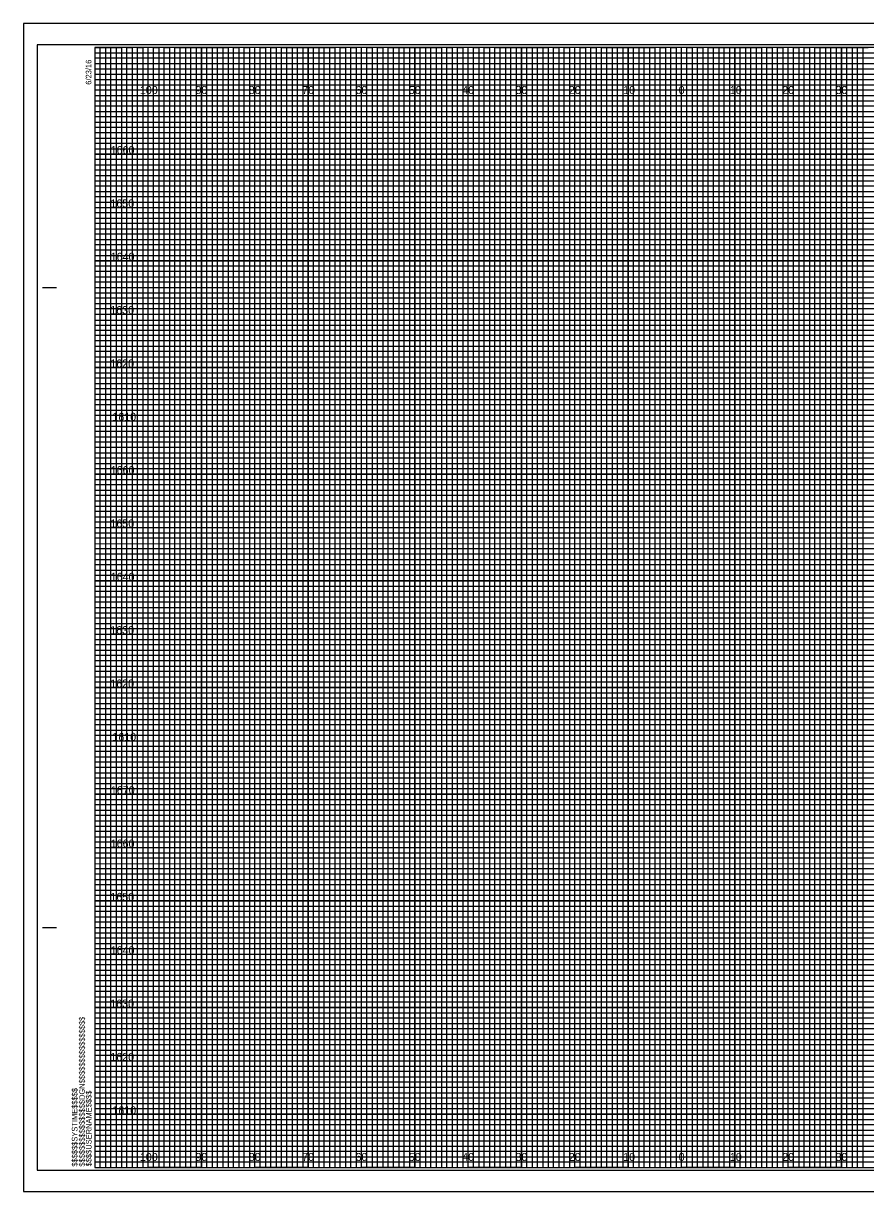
# Model space of a CAD drawing. Extents: x -13 to 323, y -5 to 6154.
# Drawn here: x -13.4 to 144.5, y 4175.5 to 4394.5 of the extents above; entities that cross this region are included whole.
import ezdxf

# ---------------------------------------------------------------- set-up
doc = ezdxf.new("R2010")
doc.units = 0
for name, color, linetype in [('Prop Retaining Wall', 7, 'Continuous'), ('Prop XS Alignment Label', 7, 'Continuous'), ('Prop XS DDE', 7, 'Continuous'), ('Prop XS DDE Elevations', 7, 'Continuous'), ('Prop XS DDE Slope Text', 7, 'Continuous'), ('Prop XS Earthwork Shape', 7, 'Continuous'), ('Prop XS Elevation Labels', 7, 'Continuous'), ('Prop XS Station Labels', 7, 'Continuous'), ('Raster_Level_0', 7, 'Continuous'), ('Scratch_Level_3', 7, 'Continuous'), ('Sheet Cutting Line CELL', 7, 'Continuous')]:
    doc.layers.add(name, color=color, linetype=linetype)

msp = doc.modelspace()

# ---------------------------------------------------------------- linework, layer by layer
at = {"layer": 'Prop Retaining Wall'}
for p, q in [((0, 4389), (260, 4389)), ((260, 4387.98), (0, 4387.98)), ((0, 4387.98), (0, 4387)), ((0, 4387), (260, 4387)), ((260, 4385.89), (0, 4385.89)), ((0, 4385.89), (0, 4384)), ((0, 4384), (320, 4384))]:
    msp.add_line(p, q, dxfattribs=at)
for points in [[(0, 4383), (270, 4383), (320, 4383), (320, 4382), (0, 4382)], [(0, 4381), (320, 4381), (320, 4379), (0, 4379)], [(0, 4378), (320, 4378), (320, 4377), (0, 4376.98)], [(0, 4376), (320, 4376), (320, 4374), (0, 4374)], [(0, 4373), (320, 4373), (320, 4372), (0, 4372)], [(0, 4371), (320, 4371), (320, 4369), (0, 4369)], [(0, 4368), (320, 4368), (320, 4367), (0, 4367)], [(0, 4366), (320, 4366), (320, 4364), (0, 4364)], [(0, 4363), (320, 4363), (320, 4362), (0, 4362)], [(0, 4361), (320, 4361), (320, 4359), (0, 4359)], [(0, 4358), (320, 4358), (320, 4357), (0, 4357)], [(0, 4356), (320, 4356), (320, 4353.95), (320, 4353), (320, 4352), (0, 4352)], [(0, 4354), (320, 4354), (320, 4353), (0, 4353)], [(0, 4351), (320, 4351), (320, 4349), (0, 4349.03)], [(0, 4349.03), (320, 4349), (320, 4348), (0, 4348)], [(0, 4347), (320, 4347), (320, 4346), (0, 4346)], [(0, 4344), (320, 4344), (320, 4343), (0, 4343)], [(0, 4342), (320, 4342), (320, 4341), (0, 4341)], [(-0.07, 4338.89), (320, 4338.89), (320, 4337.88), (-0.07, 4337.88)], [(0, 4337), (320, 4337), (320, 4336), (0, 4336)], [(0, 4334), (320, 4334), (320, 4333), (0, 4333)], [(0, 4332), (320, 4332), (320, 4331), (0, 4331)], [(0, 4329), (320, 4329), (320, 4328), (0, 4328)], [(0, 4327), (320, 4327), (320, 4326), (0, 4326)], [(0, 4324), (320, 4324), (320, 4323), (0, 4323)], [(0, 4322), (320, 4322), (320, 4321), (0, 4321)], [(0, 4319), (320, 4319), (319.99, 4317.98), (0, 4318)], [(0, 4317), (320, 4317), (320, 4316), (0, 4316)], [(0, 4314), (320, 4314), (320, 4313), (0, 4313)], [(0, 4312), (320, 4312), (320, 4311), (0, 4311)], [(0, 4309), (320, 4309), (320, 4308), (0, 4308)], [(0, 4307), (320, 4307), (320, 4306), (0, 4306)], [(0, 4304), (320, 4304), (320, 4303), (0, 4303)], [(0, 4302), (320, 4302), (320, 4301), (0, 4301)], [(0, 4299), (320, 4299), (320, 4298), (0, 4298)], [(0, 4296.99), (320.07, 4296.91), (320, 4296), (0, 4296)], [(0, 4294), (320, 4294), (320, 4293), (0, 4293)], [(0, 4292), (320, 4292), (320, 4291), (0, 4291)], [(0, 4289), (320, 4289), (320, 4288), (0, 4288)], [(0, 4287), (320, 4287), (320, 4286), (0, 4286)], [(0, 4284), (320, 4284), (320, 4283), (0, 4283)], [(0, 4282), (320, 4282), (320, 4281), (0, 4281)], [(0, 4279), (320, 4279), (320, 4278), (0, 4278)], [(0, 4277), (320, 4277), (320, 4276), (0, 4276)], [(0, 4274), (320, 4274), (320, 4273), (0, 4273)], [(0, 4272), (320, 4272), (320, 4271), (0, 4271)], [(0, 4269), (320, 4269), (320, 4268), (0, 4268)], [(0, 4267), (320, 4267), (320, 4266), (0, 4266)], [(0, 4264), (320, 4264), (320, 4263), (0, 4263)], [(0, 4262), (320, 4262), (320, 4261), (0, 4261)], [(0, 4259), (320, 4259), (319.99, 4257.98), (0, 4258)], [(0, 4257), (320, 4257), (320, 4256), (0, 4256)], [(0, 4254), (320, 4254), (320, 4253), (0, 4253)], [(0, 4252), (320, 4252), (320, 4251), (0, 4251)], [(0, 4249), (320, 4249), (320, 4248), (0, 4248)], [(0, 4247), (320, 4247), (320, 4246), (0, 4246)], [(0, 4244), (320, 4244), (320, 4243), (0, 4243)], [(0, 4242), (320, 4242), (320, 4241), (0, 4241)], [(0, 4239), (320, 4239), (320, 4238), (0, 4238)], [(0, 4236.99), (320.07, 4236.91), (320, 4236), (0, 4236)], [(0, 4234), (320, 4234), (320, 4233), (0, 4233)], [(0, 4232), (320, 4232), (320, 4231), (0, 4231)], [(0, 4229), (320, 4229), (320, 4228), (0, 4228)], [(0, 4227), (320, 4227), (320, 4226), (0, 4226)], [(0, 4224), (320, 4224), (320, 4223), (0, 4223)], [(0, 4222), (320, 4222), (320, 4221), (0, 4221)], [(0, 4219), (320, 4219), (320, 4218), (0, 4218)], [(0, 4217), (320, 4217), (320, 4216), (0, 4216)], [(0, 4214), (320, 4214), (320, 4213), (0, 4213)], [(0, 4212), (320, 4212), (320, 4211), (0, 4211)], [(0, 4209), (320, 4209), (320, 4208), (0, 4208)], [(0, 4207), (320, 4207), (320, 4206), (0, 4206)], [(0, 4204), (320, 4204), (320, 4203), (0, 4203)], [(0, 4202), (320, 4202), (320, 4201), (0, 4201)], [(0, 4199), (320, 4199), (320, 4198), (0, 4198)], [(0, 4197), (320, 4197), (320, 4196), (0, 4196)], [(0, 4194), (320, 4194), (320, 4193), (0, 4193)], [(0, 4192), (320, 4192), (320, 4191), (0, 4191)], [(0, 4189), (320, 4189), (320, 4188), (0, 4188)], [(0, 4187), (320, 4187), (320, 4186), (0, 4186)], [(0, 4184), (320, 4184), (320, 4183), (0, 4183)], [(0, 4182), (320, 4182), (320, 4181), (0, 4181)]]:
    msp.add_lwpolyline(points, dxfattribs=at)
at = {"layer": 'Prop XS Alignment Label'}
for p, q in [((-9.8, 4345), (-7.3, 4345)), ((-9.7, 4345), (-7.2, 4345)), ((-9.8, 4225), (-7.3, 4225)), ((-9.7, 4225), (-7.2, 4225)), ((0, 4180), (0, 4180)), ((0, 4180), (0, 4180)), ((0, 4180), (0, 4180)), ((0, 4180), (0, 4180)), ((0, 4180), (0, 4180)), ((0, 4180), (0, 4180)), ((0, 4180), (0, 4180))]:
    msp.add_line(p, q, dxfattribs=at)
msp.add_lwpolyline([(320, 4390), (0, 4390), (0, 4180), (320, 4180)], close=True, dxfattribs=at)
at = {"layer": 'Prop XS DDE'}
msp.add_lwpolyline([(-13.4, 4175.5), (323.3, 4175.5), (323.3, 4394.5), (-13.4, 4394.5)], close=True, dxfattribs=at)
at = {"layer": 'Prop XS DDE Elevations'}
for p, q in [((10, 4180), (10, 4390)), ((20, 4180), (20, 4390)), ((30, 4180), (30, 4390)), ((40, 4180), (40, 4390)), ((50, 4180), (50, 4390)), ((60, 4180), (60, 4390)), ((70, 4180), (70, 4390)), ((80, 4180), (80, 4390)), ((90, 4180), (90, 4390)), ((100, 4180), (100, 4390)), ((110, 4180), (110, 4390)), ((120, 4180), (120, 4390)), ((130, 4180), (130, 4390)), ((140, 4180), (140, 4390)), ((0, 4380), (320, 4380)), ((0, 4370), (320, 4370)), ((0, 4360), (320, 4360)), ((0, 4350), (320, 4350)), ((0, 4340), (320, 4340)), ((0, 4330), (320, 4330)), ((0, 4320), (320, 4320)), ((0, 4310), (320, 4310)), ((0, 4300), (320, 4300)), ((0, 4290), (320, 4290)), ((0, 4280), (320, 4280)), ((0, 4270), (320, 4270)), ((0, 4260), (320, 4260)), ((0, 4250), (320, 4250)), ((0, 4240), (320, 4240)), ((0, 4230), (320, 4230)), ((0, 4220), (320, 4220)), ((0, 4210), (320, 4210)), ((0, 4200), (320, 4200)), ((0, 4190), (320, 4190))]:
    msp.add_line(p, q, dxfattribs=at)
at = {"layer": 'Prop XS DDE Slope Text'}
msp.add_lwpolyline([(-10.8, 4179.5), (322.4, 4179.5), (322.4, 4390.5), (-10.8, 4390.5)], close=True, dxfattribs=at)
at = {"layer": 'Prop XS Earthwork Shape'}
for p, q in [((10, 4390), (0, 4390)), ((10, 4180), (10, 4390)), ((30, 4390), (20, 4390)), ((20, 4390), (20, 4180)), ((30, 4180), (30, 4390)), ((50, 4390), (40, 4390)), ((40, 4390), (40, 4180)), ((50, 4180), (50, 4390)), ((70, 4390), (60, 4390)), ((60, 4390), (60, 4180)), ((70, 4180), (70, 4390)), ((90, 4390), (80, 4390)), ((80, 4390), (80, 4180)), ((90, 4180), (90, 4390)), ((110, 4390), (100, 4390)), ((100, 4390), (100, 4180)), ((110, 4180), (110, 4390)), ((130, 4390), (120, 4390)), ((120, 4390), (120, 4180)), ((130, 4180), (130, 4390)), ((150, 4390), (140, 4390)), ((140, 4390), (140, 4180)), ((20, 4180), (10, 4180)), ((40, 4180), (30, 4180)), ((60, 4180), (50, 4180)), ((80, 4180), (70, 4180)), ((100, 4180), (90, 4180)), ((120, 4180), (110, 4180)), ((140, 4180), (130, 4180))]:
    msp.add_line(p, q, dxfattribs=at)
for points in [[(0, 4380), (320, 4380), (320, 4370), (0, 4370)], [(0, 4360), (320, 4360), (320, 4350), (0, 4350)], [(0, 4340), (320, 4340), (320, 4330), (0, 4330)], [(0, 4320), (320, 4320), (320, 4310), (0, 4310)], [(0, 4300), (320, 4300), (320, 4290), (0, 4290)], [(0, 4280), (320, 4280), (320, 4270), (0, 4270)], [(0, 4260), (320, 4260), (320, 4250), (0, 4250)], [(0, 4240), (320, 4240), (320, 4230), (0, 4230)], [(0, 4220), (320, 4220), (320, 4210), (0, 4210)], [(0, 4200), (320, 4200), (320, 4190), (0, 4190)]]:
    msp.add_lwpolyline(points, dxfattribs=at)
at = {"layer": 'Prop XS Elevation Labels'}
for points in [[(0, 4180), (1, 4180), (1, 4390), (2, 4390), (2, 4180)], [(2, 4180), (3, 4180), (3, 4390), (4, 4390), (4, 4180)], [(5, 4180), (6, 4180), (6, 4390), (7, 4390), (7, 4180)], [(7, 4180), (8, 4180), (8, 4390), (9, 4390), (9, 4180)], [(10, 4180), (11, 4180), (11, 4390), (12, 4390), (12, 4180)], [(12, 4180), (13, 4180), (13, 4390), (14, 4390), (14, 4180)], [(15, 4180), (16, 4180), (16, 4390), (17, 4390), (17, 4180)], [(17, 4180), (18, 4180), (18, 4390), (19, 4390), (19, 4180)], [(20, 4180), (21, 4180), (21, 4390), (22, 4390), (22, 4180)], [(22, 4180), (23, 4180), (23, 4390), (24, 4390), (24, 4180)], [(25, 4180), (26, 4180), (26, 4390), (27, 4390), (27, 4180)], [(27, 4180), (28, 4180), (28, 4390), (29, 4390), (29, 4180)], [(30, 4180), (31, 4180), (31, 4390), (32, 4390), (32, 4180)], [(32, 4180), (33, 4180), (33, 4390), (34, 4390), (34, 4180)], [(35, 4180), (36, 4180), (36, 4390), (37, 4390), (37, 4180)], [(37, 4180), (38, 4180), (38, 4390), (39, 4390), (39, 4180)], [(40, 4180), (41, 4180), (41, 4390), (42, 4390), (42, 4180)], [(42, 4180), (43, 4180), (43, 4390), (44, 4390), (44, 4180)], [(45, 4180), (46, 4180), (46, 4390), (47, 4390), (47, 4180)], [(47, 4180), (48, 4180), (48, 4390), (49, 4390), (49, 4180)], [(50, 4180), (51, 4180), (51, 4390), (52, 4390), (52, 4180)], [(52, 4180), (53, 4180), (53, 4390), (54, 4390), (54, 4180)], [(55, 4180), (56, 4180), (56, 4390), (57, 4390), (57, 4180)], [(57, 4180), (58, 4180), (58, 4390), (59, 4390), (59, 4180)], [(60, 4180), (61, 4180), (61, 4390), (62, 4390), (62, 4180)], [(62, 4180), (63, 4180), (63, 4390), (64, 4390), (64, 4180)], [(65, 4180), (66, 4180), (66, 4390), (67, 4390), (67, 4180)], [(67, 4180), (68, 4180), (68, 4390), (69, 4390), (69, 4180)], [(70, 4180), (71, 4180), (71, 4390), (72, 4390), (72, 4180)], [(72, 4180), (73, 4180), (73, 4390), (74, 4390), (74, 4180)], [(75, 4180), (76, 4180), (76, 4390), (77, 4390), (77, 4180)], [(77, 4180), (78, 4180), (78, 4390), (79, 4390), (79, 4180)], [(80, 4180), (81, 4180), (81, 4390), (82, 4390), (82, 4180)], [(82, 4180), (83, 4180), (83, 4390), (84, 4390), (84, 4180)], [(85, 4180), (86, 4180), (86, 4390), (87, 4390), (87, 4180)], [(87, 4180), (88, 4180), (88, 4390), (89, 4390), (89, 4180)], [(90, 4180), (91, 4180), (91, 4390), (92, 4390), (92, 4180)], [(92, 4180), (93, 4180), (93, 4390), (94, 4390), (94, 4180)], [(95, 4180), (96, 4180), (96, 4390), (97, 4390), (97, 4180)], [(97, 4180), (98, 4180), (98, 4390), (99, 4390), (99, 4180)], [(100, 4180), (101, 4180), (101, 4390), (102, 4390), (102, 4180)], [(102, 4180), (103, 4180), (103, 4390), (104, 4390), (104, 4180)], [(105, 4180), (106, 4180), (106, 4390), (107, 4390), (107, 4180)], [(107, 4180), (108, 4180), (108, 4390), (109, 4390), (109, 4180)], [(110, 4180), (111, 4180), (111, 4390), (112, 4390), (112, 4180)], [(112, 4180), (113, 4180), (113, 4390), (114, 4390), (114, 4180)], [(115, 4180), (116, 4180), (116, 4390), (117, 4390), (117, 4180)], [(117, 4180), (118, 4180), (118, 4390), (119, 4390), (119, 4180)], [(120, 4180), (121, 4180), (121, 4390), (122, 4390), (122, 4180)], [(122, 4180), (123, 4180), (123, 4390), (124, 4390), (124, 4180)], [(125, 4180), (126, 4180), (126, 4390), (127, 4390), (127, 4180)], [(127, 4180), (128, 4180), (128, 4390), (129, 4390), (129, 4180)], [(130, 4180), (131, 4180), (131, 4390), (132, 4390), (132, 4180)], [(132, 4180), (133, 4180), (133, 4390), (134, 4390), (134, 4180)], [(135, 4180), (136, 4180), (136, 4390), (137, 4390), (137, 4180)], [(137, 4180), (138, 4180), (138, 4390), (139, 4390), (139, 4180)], [(140, 4180), (141, 4180), (141, 4390), (142, 4390), (142, 4180)], [(142, 4180), (143, 4180), (143, 4390), (144, 4390), (144, 4180)]]:
    msp.add_lwpolyline(points, dxfattribs=at)
at = {"layer": 'Prop XS Station Labels'}
for points in [[(0, 4390), (5, 4390), (5, 4180), (15, 4180), (15, 4390), (25, 4390), (25, 4180), (35, 4180), (35, 4390), (45, 4390), (45, 4180), (55, 4180), (55, 4390), (65, 4390), (65, 4180), (75, 4180), (75, 4390), (85, 4390), (85, 4180), (95, 4180), (95, 4390), (105, 4390), (105, 4180), (115, 4180), (115, 4390), (125, 4390), (125, 4180), (135, 4180), (135, 4390), (145, 4390)], [(0, 4385), (275, 4385)], [(0, 4365), (320, 4365), (320, 4375), (0, 4375)], [(0, 4345), (320, 4345), (320, 4355), (0, 4355)], [(0, 4325), (320, 4325), (320, 4335), (0, 4335)], [(0, 4305), (320, 4305), (320, 4315), (0, 4315)], [(0, 4285), (320, 4285), (320, 4295), (0, 4295)], [(0, 4265), (320, 4265), (320, 4275), (0, 4275)], [(0, 4245), (320, 4245), (320, 4255), (0, 4255)], [(0, 4225), (320, 4225), (320, 4235), (0, 4235)], [(0, 4205), (320, 4205), (320, 4215), (0, 4215)], [(0, 4185), (320, 4185), (320, 4195), (0, 4195)]]:
    msp.add_lwpolyline(points, dxfattribs=at)
at = {"layer": 'Sheet Cutting Line CELL'}
for p, q in [((323.3, 4394.5), (-13.4, 4394.5)), ((-13.4, 4394.5), (-13.4, 4175.5)), ((-13.4, 4175.5), (323.3, 4175.5))]:
    msp.add_line(p, q, dxfattribs=at)

# ---------------------------------------------------------------- texts
at = {"layer": 'Prop XS Alignment Label'}
for s, p in [('6/23/16', (-0.65, 4383)), ('$$$$$$$$$$$$$$$$DGN$$$$$$$$$$$$$$$$', (-1.88, 4180.18)), ('$$$$$$SYSTIME$$$$$', (-3.26, 4180.18)), ('$$$$USERNAME$$$$', (-0.62, 4180.23))]:
    msp.add_text(s, height=1.05, rotation=90, dxfattribs=at).set_placement(p)
at = {"layer": 'Raster_Level_0'}
for s, p in [('100', (8.44, 4381.25)), ('90', (18.86, 4381.25)), ('80', (28.86, 4381.25)), ('70', (38.86, 4381.25)), ('60', (48.86, 4381.25)), ('50', (58.86, 4381.25)), ('40', (68.86, 4381.25)), ('30', (78.86, 4381.25)), ('20', (88.86, 4381.25)), ('10', (99.04, 4381.25)), ('0', (109.45, 4381.25)), ('0', (109.45, 4381.25)), ('10', (119.04, 4381.25)), ('20', (128.86, 4381.25)), ('30', (138.86, 4381.25)), ('100', (8.44, 4181.25)), ('90', (18.86, 4181.25)), ('80', (28.86, 4181.25)), ('70', (38.86, 4181.25)), ('60', (48.86, 4181.25)), ('50', (58.86, 4181.25)), ('40', (68.86, 4181.25)), ('30', (78.86, 4181.25)), ('20', (88.86, 4181.25)), ('10', (99.04, 4181.25)), ('0', (109.45, 4181.25)), ('0', (109.45, 4181.25)), ('10', (119.04, 4181.25)), ('20', (128.86, 4181.25)), ('30', (138.86, 4181.25))]:
    msp.add_text(s, height=1.5, dxfattribs=at).set_placement(p)
at = {"layer": 'Scratch_Level_3'}
for s, p in [('1660', (2.97, 4370)), ('1650', (2.92, 4360)), ('1640', (2.97, 4350)), ('1630', (2.89, 4340)), ('1620', (2.9, 4330)), ('1610', (3.28, 4320)), ('1660', (2.97, 4310)), ('1650', (2.92, 4300)), ('1640', (2.97, 4290)), ('1630', (2.89, 4280)), ('1620', (2.9, 4270)), ('1610', (3.28, 4260)), ('1670', (3, 4250)), ('1660', (2.97, 4240)), ('1650', (2.92, 4230)), ('1640', (2.97, 4220)), ('1630', (2.89, 4210)), ('1620', (2.9, 4200)), ('1610', (3.28, 4190))]:
    msp.add_text(s, height=1.5, dxfattribs=at).set_placement(p)

doc.saveas('drawing.dxf')
